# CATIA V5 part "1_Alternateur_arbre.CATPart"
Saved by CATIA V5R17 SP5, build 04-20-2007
Part number: 1_Alternateur_arbre
Bounding box of the stored display mesh (mm): x -9.942 to 9.942, y -60 to 29, z -9.942 to 9.942
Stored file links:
  C:\Users\Frédéric\Documents\WF\STSCPI 09-11\Projets\Projet multiplicateur eolienne\Maquette eolienne\1_Alternateur_arbre.CATPart
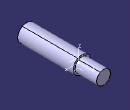
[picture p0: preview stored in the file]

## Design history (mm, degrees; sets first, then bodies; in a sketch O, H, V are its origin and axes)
AxisSystem1: origin (0, 0, 0), X (1, 0, 0), Y (0, 1, 0), Z (0, 0, 1)
Body1 (main body)
  Sketch1 on YZ plane of AxisSystem1, origin (0, 0, 0), H (0, 1, 0), V (0, 0, 1)
    line L1 (29, 0) -> (29, 8)
    line L2 (29, 8) -> (4, 8)
    line L3 (4, 8) -> (4, 10)
    line L4 (4, 10) -> (-60, 10)
    line L5 (-60, 10) -> (-60, 0)
    point P6 (-60, 0)
    line L6 (-60, 0) -> (29, 0)
    length L2 = 25
    distance L3 V = 4
    length L1 = 8
    length L5 = 10
    distance V L5 = 60
    vertical: L1 V, L3 V, L5 V
    horizontal: L2 H, L4 H, L6 H
    coincidence: P6 H
  Shaft1: profile Sketch1, axis Sketch1.L6, angle 360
